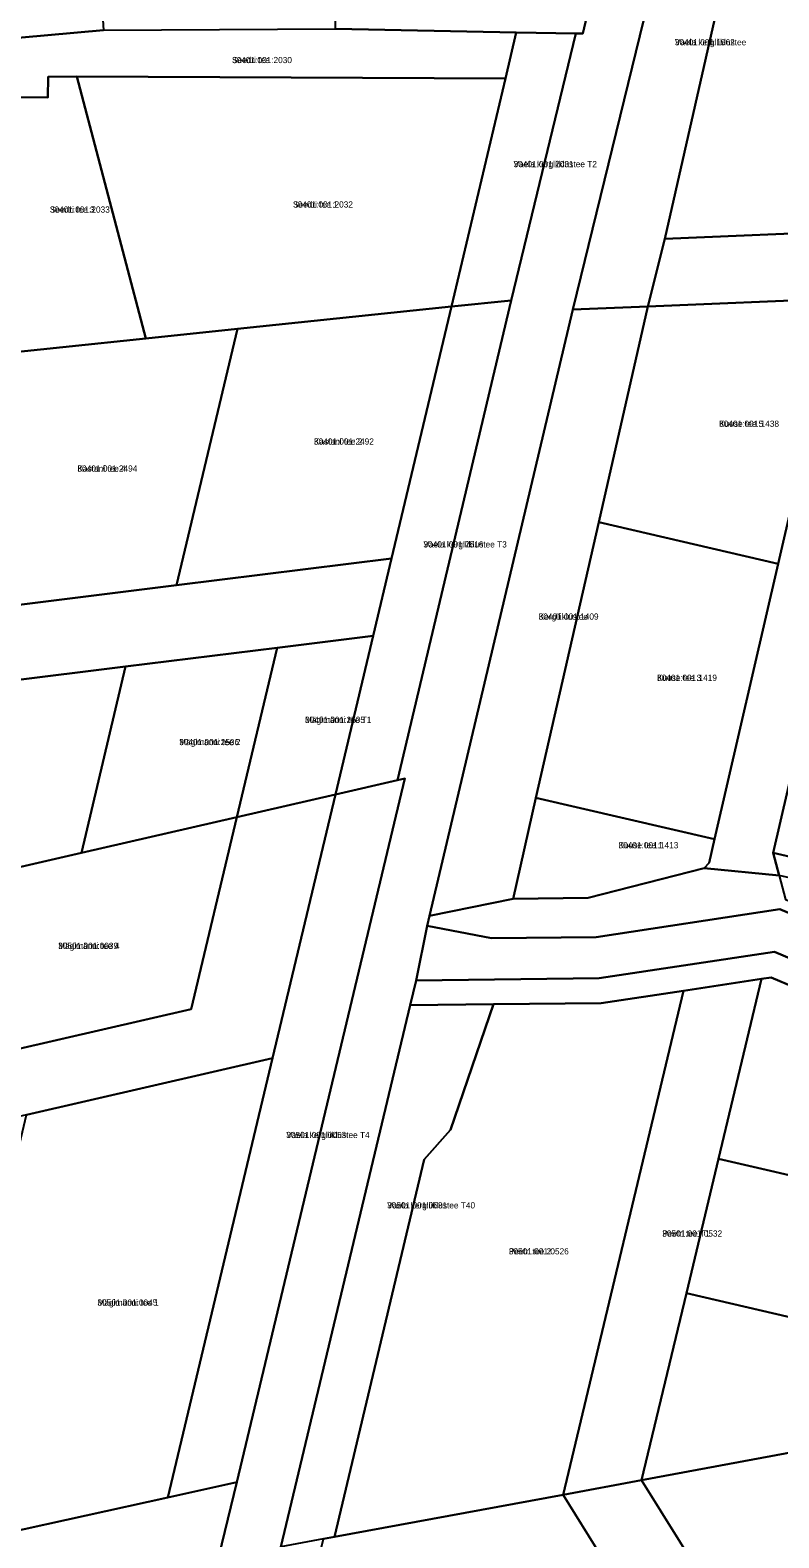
# Model space of a CAD drawing. Extents: x 542681 to 554572, y 6566489 to 6580482.
# Drawn here: x 546596.4 to 546777.7, y 6576513.1 to 6576877.8 of the extents above; entities that cross this region are included whole.
import ezdxf

# ---------------------------------------------------------------- set-up
doc = ezdxf.new("R2010")
doc.units = 0
for name, color, linetype in [('L_AADRESS', 7, 'Continuous'), ('PIIR', 7, 'Continuous'), ('TUNNUS', 7, 'Continuous')]:
    doc.layers.add(name, color=color, linetype=linetype)

msp = doc.modelspace()

# ---------------------------------------------------------------- linework, layer by layer
at = {"layer": 'PIIR'}
for points in [[(546404.82, 6576900.23), (546408.54, 6576958.81), (546409.12, 6576968.23), (546554.54, 6576931.7), (546611.92, 6576912.76), (546614.2, 6576877.84), (546566.47, 6576873.53), (546549.64, 6576872.04), (546548.97, 6576861.43), (546497.57, 6576858.02), (546489.69, 6576789.03), (546466.28, 6576787.63), (546431.29, 6576785.34), (546397.62, 6576783.16), (546402.28, 6576860.46)], [(546670.18, 6576935.4), (546671.44, 6576963.09), (546703.69, 6576952.46), (546703.09, 6576949.56), (546744.69, 6576938.56), (546742.3, 6576928.03), (546730.2, 6576876.99), (546728.53, 6576877.02), (546714.12, 6576877.29), (546670.36, 6576878.16)], [(546727.78, 6576810.22), (546751.7, 6576907.82), (546761.4, 6576936.33), (546763.16, 6576950.29), (546777.26, 6576947.19), (546750.08, 6576827.31), (546745.99, 6576810.98)], [(546777.26, 6576947.19), (546815.06, 6576938.44), (546815.33, 6576930.58), (546818.1, 6576924.06), (546796.17, 6576829.25), (546750.08, 6576827.31)], [(546566.47, 6576873.53), (546614.2, 6576877.84), (546670.36, 6576878.16), (546714.12, 6576877.29), (546711.5, 6576866.17), (546607.68, 6576866.59), (546600.81, 6576866.56), (546600.73, 6576861.54), (546578.18, 6576861.64), (546578.25, 6576871.35)], [(546728.53, 6576877.02), (546712.9, 6576812.45), (546698.41, 6576810.96), (546711.5, 6576866.17), (546714.12, 6576877.29)], [(546624.42, 6576803.23), (546584.15, 6576799.03), (546577.97, 6576798.4), (546578.18, 6576861.64), (546600.73, 6576861.54), (546600.81, 6576866.56), (546607.68, 6576866.59)], [(546698.41, 6576810.96), (546646.59, 6576805.55), (546624.42, 6576803.23), (546607.68, 6576866.59), (546711.5, 6576866.17)], [(546792.38, 6576812.89), (546807.51, 6576813.51), (546801.91, 6576789.31), (546793.85, 6576754.47), (546789.44, 6576735.41), (546783.45, 6576709.49), (546776.34, 6576678.79), (546777.76, 6576673.32), (546759.61, 6576675.14), (546760.8, 6576676.36), (546762.13, 6576682.09), (546777.54, 6576748.73)], [(546631.88, 6576743.54), (546646.59, 6576805.55), (546698.41, 6576810.96), (546683.91, 6576749.98)], [(546683.91, 6576749.98), (546698.41, 6576810.96), (546712.9, 6576812.45), (546685.35, 6576696.37), (546670.38, 6576692.92), (546679.48, 6576731.3)], [(546727.78, 6576810.22), (546745.99, 6576810.98), (546734.09, 6576758.79), (546718.89, 6576692.1), (546713.33, 6576667.72), (546693.12, 6576663.61)], [(546745.99, 6576810.98), (546792.38, 6576812.89), (546777.54, 6576748.73), (546734.09, 6576758.79)], [(546569.14, 6576735.76), (546584.15, 6576799.03), (546624.42, 6576803.23), (546646.59, 6576805.55), (546631.88, 6576743.54)], [(546734.09, 6576758.79), (546777.54, 6576748.73), (546762.13, 6576682.09), (546718.89, 6576692.1)], [(546262.71, 6576649.2), (546255.54, 6576664.77), (546304.45, 6576679.9), (546351.66, 6576694.5), (546365.04, 6576698.64), (546415.21, 6576714.16), (546428.85, 6576718.38), (546439.44, 6576719.69), (546474.17, 6576723.99), (546508.9, 6576728.3), (546543.64, 6576732.6), (546569.14, 6576735.76), (546631.88, 6576743.54), (546683.91, 6576749.98), (546679.48, 6576731.3), (546656.19, 6576728.41), (546619.51, 6576723.87), (546531.36, 6576712.94), (546474.89, 6576705.94), (546467.91, 6576705.08), (546427, 6576700.01), (546409.2, 6576694.51), (546357.27, 6576678.44), (546304.01, 6576661.97)], [(546646.47, 6576687.45), (546656.19, 6576728.41), (546679.48, 6576731.3), (546670.38, 6576692.92)], [(546608.81, 6576678.79), (546619.51, 6576723.87), (546656.19, 6576728.41), (546646.47, 6576687.45)], [(546537.6, 6576662.39), (546531.36, 6576712.94), (546619.51, 6576723.87), (546608.81, 6576678.79), (546571.02, 6576670.08)], [(546783.45, 6576709.49), (546834.11, 6576697.77), (546826.98, 6576667.16), (546776.34, 6576678.79)], [(546655.13, 6576629.17), (546670.38, 6576692.92), (546685.35, 6576696.37), (546687.1, 6576696.8), (546646.49, 6576526.56), (546629.77, 6576522.87)], [(546458.74, 6576558.56), (546457.46, 6576600.12), (546477.97, 6576604.84), (546524.12, 6576615.41), (546559.91, 6576623.69), (546635.37, 6576641.02), (546646.47, 6576687.45), (546670.38, 6576692.92), (546655.13, 6576629.17), (546595.53, 6576615.46), (546530.03, 6576600.41), (546479.75, 6576588.84), (546474.05, 6576580.83), (546474.7, 6576561.17), (546477.55, 6576554.2), (546514.39, 6576562.66), (546517.62, 6576548.51), (546508.39, 6576546.43), (546474.87, 6576538.69), (546461.45, 6576536.13), (546457.19, 6576551.53)], [(546718.89, 6576692.1), (546762.13, 6576682.09), (546760.8, 6576676.36), (546759.61, 6576675.14), (546731.56, 6576667.93), (546713.33, 6576667.72)], [(546559.91, 6576623.69), (546571.02, 6576670.08), (546608.81, 6576678.79), (546646.47, 6576687.45), (546635.37, 6576641.02)], [(546777.76, 6576673.32), (546776.34, 6576678.79), (546826.98, 6576667.16), (546809.77, 6576651.68), (546799.63, 6576663.08), (546788.52, 6576670.88)], [(546693.12, 6576663.61), (546713.33, 6576667.72), (546731.56, 6576667.93), (546759.61, 6576675.14), (546777.76, 6576673.32), (546779.3, 6576667.53), (546787.05, 6576664.58), (546788.52, 6576670.88), (546799.63, 6576663.08), (546809.77, 6576651.68), (546846.67, 6576610.31), (546861.96, 6576593.14), (546888.43, 6576563.48), (546891.72, 6576561.48), (546923.44, 6576542.21), (546958.69, 6576520.81), (546956.78, 6576514.71), (546885, 6576558.31), (546796.81, 6576657.2), (546777.95, 6576665.16), (546733.46, 6576658.45), (546708.16, 6576658.15), (546692.54, 6576661.18)], [(546688.43, 6576641.93), (546689.88, 6576647.97), (546734.22, 6576648.46), (546776.62, 6576654.85), (546790.81, 6576648.86), (546877.51, 6576551.65), (546870.64, 6576550.36), (546823.18, 6576603.64), (546787.29, 6576643.82), (546775.84, 6576648.67), (546773.49, 6576648.32), (546754.59, 6576645.44), (546734.71, 6576642.48), (546708.6, 6576642.18)], [(546725.45, 6576523.53), (546754.59, 6576645.44), (546773.49, 6576648.32), (546763.11, 6576604.8), (546755.3, 6576572.28), (546744.48, 6576527.09)], [(546763.11, 6576604.8), (546773.49, 6576648.32), (546775.84, 6576648.67), (546787.29, 6576643.82), (546823.18, 6576603.64), (546820.36, 6576591.53)], [(546657.12, 6576510.94), (546688.43, 6576641.93), (546708.6, 6576642.18), (546698.16, 6576611.79), (546691.84, 6576604.59), (546670.07, 6576513.34), (546667.47, 6576512.87)], [(546698.16, 6576611.79), (546708.6, 6576642.18), (546734.71, 6576642.48), (546754.59, 6576645.44), (546725.45, 6576523.53), (546670.07, 6576513.34), (546691.84, 6576604.59)], [(546586.39, 6576577.17), (546595.53, 6576615.46), (546655.13, 6576629.17), (546629.77, 6576522.87), (546570.31, 6576509.8), (546574.33, 6576526.81)], [(546755.3, 6576572.28), (546763.11, 6576604.8), (546820.36, 6576591.53), (546812.97, 6576558.89)], [(546744.48, 6576527.09), (546755.3, 6576572.28), (546812.97, 6576558.89), (546808.4, 6576538.9)], [(546808.76, 6576404.5), (546788.11, 6576402.28), (546769.61, 6576375.55), (546738.77, 6576396.97), (546742.78, 6576413.53), (546748.62, 6576412.11), (546750.02, 6576417.99), (546744.18, 6576419.34), (546763.17, 6576497.07), (546744.48, 6576527.09), (546808.4, 6576538.9), (546870.64, 6576550.36), (546874.28, 6576546.32), (546887.95, 6576538.03), (546857.41, 6576512.26), (546814.01, 6576496.22), (546804.36, 6576482.32), (546783.04, 6576441.13), (546811.38, 6576421.46), (546817.56, 6576417.2)], [(546646.49, 6576526.56), (546616.71, 6576404.29), (546590.47, 6576410.68), (546577.85, 6576359.04), (546584.48, 6576335.17), (546576.28, 6576333.65), (546575.03, 6576338.15), (546572.7, 6576346.55), (546569.62, 6576357.65), (546556.45, 6576358.73), (546569.36, 6576411.76), (546541.59, 6576418.53), (546544.25, 6576458.88), (546306.94, 6576413.5), (546297.41, 6576450.08), (546351.11, 6576461.73), (546391.75, 6576470.68), (546432.11, 6576479.52), (546463.07, 6576486.32), (546476.48, 6576489.26), (546519.33, 6576498.66), (546570.31, 6576509.8), (546629.77, 6576522.87)], [(546742.78, 6576413.53), (546738.77, 6576396.97), (546722.91, 6576407.95), (546743.75, 6576494.19), (546725.45, 6576523.53), (546744.48, 6576527.09), (546763.17, 6576497.07), (546744.18, 6576419.34)], [(546743.75, 6576494.19), (546722.91, 6576407.95), (546668.99, 6576445.38), (546653.57, 6576456.05), (546667.47, 6576512.87), (546670.07, 6576513.34), (546725.45, 6576523.53)]]:
    msp.add_lwpolyline(points, close=True, dxfattribs=at)
for points in [[(546972.19, 6575582.98), (546919.43, 6575661.06), (546891.5, 6575702.3), (546803.37, 6575812.86), (546766.95, 6575854.47), (546633.55, 6576008.16), (546610.86, 6576042.57), (546591.44, 6576083.44), (546580.29, 6576117.69), (546573.11, 6576160.41), (546571.31, 6576185.39), (546572.31, 6576214.96), (546575.07, 6576236.09), (546582.12, 6576269.91), (546591.13, 6576300.14), (546600.62, 6576338.16), (546616.71, 6576404.29), (546646.49, 6576526.56), (546687.1, 6576696.8), (546685.35, 6576696.37), (546712.9, 6576812.45), (546728.53, 6576877.02), (546730.2, 6576876.99), (546742.3, 6576928.03)], [(546823.76, 6576883.77), (546815.07, 6576846.2), (546807.51, 6576813.51), (546792.38, 6576812.89), (546745.99, 6576810.98), (546750.08, 6576827.31), (546796.17, 6576829.25), (546818.1, 6576924.06)], [(546751.7, 6576907.82), (546727.78, 6576810.22), (546693.12, 6576663.61), (546692.54, 6576661.18), (546689.88, 6576647.97), (546688.43, 6576641.93), (546657.12, 6576510.94), (546645.39, 6576461.81), (546615.69, 6576340.94), (546602.37, 6576283.48), (546595.51, 6576248.17), (546587.48, 6576214.56), (546588.02, 6576162.19), (546594.9, 6576121.27), (546619.26, 6576057.48), (546651.28, 6576008.01), (546787.27, 6575853.06), (546828.93, 6575804.31), (546862.85, 6575764.54), (546888.29, 6575731.25), (546903.72, 6575711.07), (546934.06, 6575666.25), (546987.14, 6575587.78)], [(547083.85, 6576427.63), (546877.51, 6576551.65), (546790.81, 6576648.86), (546776.62, 6576654.85), (546734.22, 6576648.46), (546689.88, 6576647.97), (546692.54, 6576661.18), (546708.16, 6576658.15), (546733.46, 6576658.45), (546777.95, 6576665.16), (546796.81, 6576657.2), (546885, 6576558.31), (546956.78, 6576514.71), (547074.32, 6576443.23)]]:
    msp.add_lwpolyline(points, dxfattribs=at)

# ---------------------------------------------------------------- texts
at = {"layer": 'L_AADRESS'}
for s, p in [('Vaela kergliiklustee', (546752.52, 6576874.15)), ('Seedri tee', (546645.3, 6576869.85)), ('Vaela kergliiklustee T2', (546713.47, 6576844.67)), ('Seedri tee 1', (546660.07, 6576834.91)), ('Seedri tee 3', (546601.2, 6576833.68)), ('Kuuse tee 5', (546763.24, 6576781.87)), ('Kastani tee 2', (546665.14, 6576777.57)), ('Kastani tee 4', (546607.87, 6576771.03)), ('Vaela kergliiklustee T3', (546691.64, 6576752.68)), ('Kergliiklustee', (546719.55, 6576735.22)), ('Kuuse tee 3', (546748.21, 6576720.42)), ('Mägimänni tee T1', (546662.97, 6576710.24)), ('Mägimänni tee 2', (546632.5, 6576704.86)), ('Kuuse tee 1', (546738.87, 6576679.91)), ('Mägimänni tee 4', (546603.2, 6576655.57)), ('Vaela kergliiklustee T4', (546658.44, 6576609.81)), ('Vaela kergliiklustee T40', (546682.86, 6576592.79)), ('Peetri tee T1', (546749.47, 6576585.98)), ('Peetri tee 2', (546712.33, 6576581.67)), ('Mägimänni tee 1', (546612.72, 6576569.27))]:
    msp.add_text(s, height=1.5, dxfattribs=at).set_placement(p)
at = {"layer": 'TUNNUS'}
for s, p in [('30401:001:1962', (546752.52, 6576874.15)), ('30401:001:2030', (546645.3, 6576869.85)), ('30401:001:2031', (546713.47, 6576844.67)), ('30401:001:2032', (546660.07, 6576834.91)), ('30401:001:2033', (546601.2, 6576833.68)), ('30401:001:1438', (546763.24, 6576781.87)), ('30401:001:2492', (546665.14, 6576777.57)), ('30401:001:2494', (546607.87, 6576771.03)), ('30401:001:2516', (546691.64, 6576752.68)), ('30401:001:1409', (546719.55, 6576735.22)), ('30401:001:1419', (546748.21, 6576720.42)), ('30401:001:2505', (546662.97, 6576710.24)), ('30401:001:2506', (546632.5, 6576704.86)), ('30401:001:1413', (546738.87, 6576679.91)), ('30501:001:0039', (546603.2, 6576655.57)), ('30501:001:0053', (546658.44, 6576609.81)), ('30501:001:0531', (546682.86, 6576592.79)), ('30501:001:0532', (546749.47, 6576585.98)), ('30501:001:0526', (546712.33, 6576581.67)), ('30501:001:0045', (546612.72, 6576569.27))]:
    msp.add_text(s, height=1.5, dxfattribs=at).set_placement(p)

doc.saveas('drawing.dxf')
